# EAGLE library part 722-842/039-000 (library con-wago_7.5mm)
Serie 722, Federleiste mit Verriegelungsklinken / Series 722, Female connector with locking levers Polzahl / Pole No.: 12 Farbe / Color: lichtgrau / light gray Stand: 01.01.2012. Die jeweils aktuellen Daten zu diesem Artikel finden Sie in unserem Produktkatalog, den Sie unter www.wago.com einsehen können. As of: 01/01/2012. Please find the newest data for this article in our product catalogue, which can be viewed under www.wago.com.
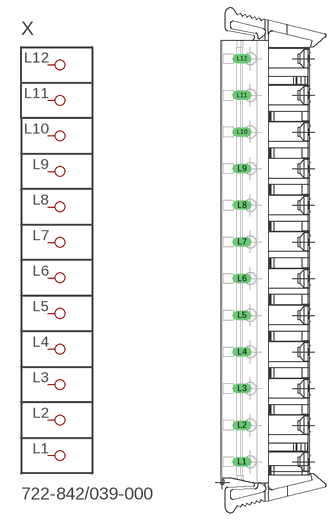
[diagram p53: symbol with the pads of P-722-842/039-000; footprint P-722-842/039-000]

Designator prefix X

## 722-842/039-000  [P-722-842/039-000]
L1  P1
L2  P2
L3  P3
L4  P4
L5  P5
L6  P6
L7  P7
L8  P8
L9  P9
L10  P10
L11  P11
L12  P12

## Footprint P-722-842/039-000 (pad centres in mm)
drill 1.3 long: L1 -5.872,-41.25; L2 -5.872,-33.75; L3 -5.872,-26.25; L4 -5.872,-18.75; L5 -5.872,-11.25; L6 -5.872,-3.75; L7 -5.872,3.75; L8 -5.872,11.25; L9 -5.872,18.75; L10 -5.872,26.25; L11 -5.872,33.75; L12 -5.872,41.25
